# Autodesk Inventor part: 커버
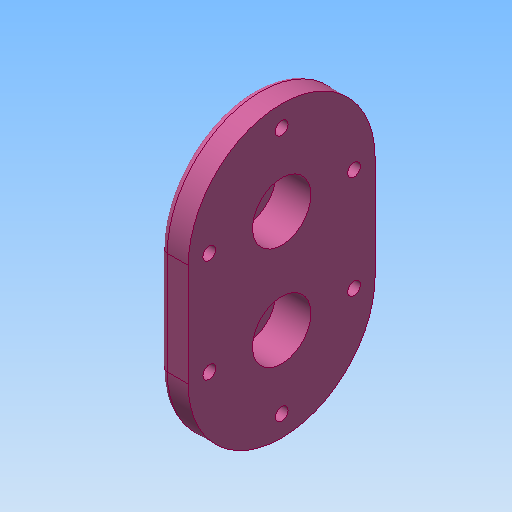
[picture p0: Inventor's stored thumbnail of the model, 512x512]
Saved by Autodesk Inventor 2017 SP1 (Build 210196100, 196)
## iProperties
Created: 2019-03
Part Number: 커버
Material: 알루미늄 6061
Document SubType Name: Modeling
Designer: mduedu
Density: 1 g/cm^3
Appearance: 분홍색
Author: mduedu
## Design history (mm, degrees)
sketch "스케치1"
  geometry: L1 (-62, 40)-(62, 40); L2 (62, 40)-(62, -40); L3 (62, -40)-(-62, -40); L4 (-62, -40)-(-62, 40); L5 (-62, 40)-(62, -40); L6 (62, 40)-(-62, -40); 1 further point
  constraints: 12 end point, 2 midpoint, 2 parallel, 1 horizontal, 1 perpendicular
  dimensions: "d59" = 124 distance of L2.end L3.end; "d60" = 80 distance of L1.end L2.end
extrude "돌출1" new body sketch "스케치1" distance "d4" = 12; taper "d5" = 0 deg
fillet "모깎기4"
fillet "모깎기5"
sketch "스케치2"
  geometry: L1 (-20, -22)-(20, -22); L2 (20, -22)-(20, 22); L3 (20, 22)-(-20, 22); L4 (-20, 22)-(-20, -22); L5 (-20, -22)-(20, 22); L6 (20, -22)-(-20, 22); 3 further points
  constraints: 12 end point, 4 midpoint, 2 horizontal alignment, 2 parallel, 1 horizontal, 1 perpendicular, 4 other
  dimensions: "d6" = 40 distance between parallel lines of L2 L4; "d8" = 44 distance between parallel lines of L1 L3
extrude "돌출2" join sketch "스케치2" distance "d9" = 10; taper "d10" = 0 deg
fillet "모깎기2" dims "d12" = 3
sketch "스케치3"
  geometry: L1 (-31, -22)-(31, -22); L2 (31, -22)-(31, 22); L3 (31, 22)-(-31, 22); L4 (-31, 22)-(-31, -22); L5 (-31, -22)-(31, 22); L6 (31, -22)-(-31, 22); A1 r 31 centre (0, 22) between (31, 22) and (0, 53); A2 r 31 centre (0, -22) between (31, -22) and (0, -53); 7 further points
  constraints: 12 end point, 6 midpoint, 4 coincident, 4 point on circle, 2 centre point, 2 parallel, 2 vertical alignment, 1 horizontal, 1 perpendicular
  dimensions: "d76" = 44 distance between parallel lines of L1 L3; "d78" = 62 distance between parallel lines of L2 L4
hole "구멍2" sketch "스케치3" at (0, 53), (31, 22), (31, -22), (-31, -22), (-31, 22), (0, -53) diameter "d28" = 5.5; stored, may be unused: countersink angle "d32" = 90 deg, drill point angle "d34" = 118 deg; dims "d29" = 6, "d30" = 4, "d31" = 2, "d33" = 8
sketch "스케치10"
  geometry: L1 (40, -22)-(40, 22) reference; L2 (-40, 22)-(-40, -22) reference; L3 (23, -22)-(23, 22) reference; L4 (-23, 22)-(-23, -22) reference; C1 r 2.75 at (-31, 22) reference; C2 r 2.75 at (31, -22) reference; C3 r 2.75 at (0, 53) reference; C4 r 2.75 at (31, 22) reference; C5 r 2.75 at (-31, -22) reference; C6 r 2.75 at (0, -53) reference; A1 r 40 centre (0, -22) between (-40, -22) and (40, -22) reference; A2 r 40 centre (0, 22) between (40, 22) and (-40, 22) reference; A3 r 23 centre (0, -22) between (-23, -22) and (23, -22) reference; A4 r 23 centre (0, 22) between (23, 22) and (-23, 22) reference; 7 further points
  constraints: 6 coincident
hole "구멍5" sketch "스케치10" at (0, 53), (31, 22), (31, -22), (0, -53), (-31, -22), (-31, 22) diameter "d79" = 11; stored, may be unused: countersink angle "d83" = 90 deg, drill point angle "d85" = 0 deg; dims "d80" = 6, "d81" = 4, "d82" = 2, "d84" = 5.4
fillet "모깎기3" dims "d68" = 3
sketch "스케치6"
  geometry: C1 r 12.5 at (0, 22); 1 further point
  constraints: 1 centre point, 1 vertical alignment
  dimensions: "d43" = 25 diameter of C1; "d45" = 22 distance of C1.centre point (0, 0)
extrude "돌출5" cut sketch "스케치6" distance "d47" = 15; taper "d48" = 0 deg
node "솔리드1"
mirror "대칭1"
node "투영된 루프5"
